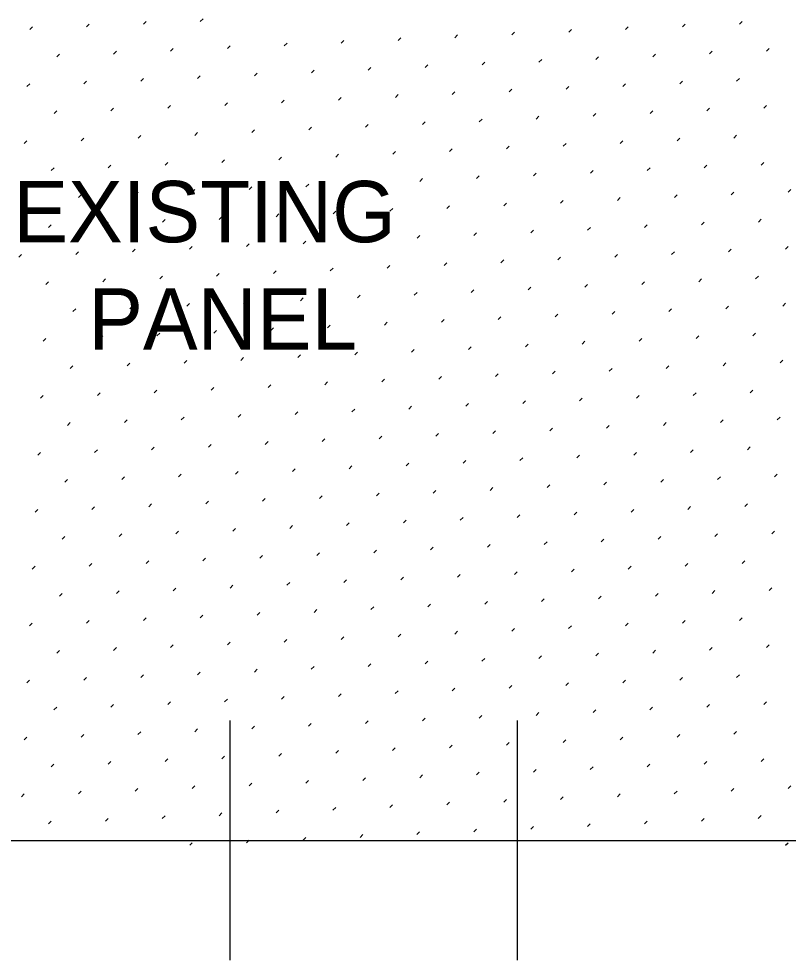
# Model space of a CAD drawing. Extents: x 49991.4 to 50021, y 49987.6 to 50011.4.
# Drawn here: x 50006.722 to 50007.726, y 49996.134 to 49997.362 of the extents above; entities that cross this region are included whole.
import ezdxf

# ---------------------------------------------------------------- set-up
doc = ezdxf.new("R2010")
doc.units = 0
for name, color, linetype in [('Level 1', 7, 'Continuous'), ('Level 10', 7, 'Continuous'), ('Level 2', 7, 'Continuous'), ('Level 4', 7, 'Continuous')]:
    doc.layers.add(name, color=color, linetype=linetype)

msp = doc.modelspace()

# ---------------------------------------------------------------- linework, layer by layer
at = {"layer": 'Level 1'}
msp.add_line((50002.3098, 49996.2901), (50007.9348, 49996.2901), dxfattribs=at)
at = {"layer": 'Level 10'}
for p, q in [((50006.7362, 49997.3477), (50006.7397, 49997.3512)), ((50006.8104, 49997.3512), (50006.814, 49997.3548)), ((50006.8847, 49997.3548), (50006.8882, 49997.3583)), ((50006.9589, 49997.3583), (50006.9625, 49997.3619)), ((50007.5141, 49997.3478), (50007.5176, 49997.3513)), ((50007.5883, 49997.3513), (50007.5919, 49997.3548)), ((50007.6626, 49997.3548), (50007.6661, 49997.3584)), ((50007.2913, 49997.3371), (50007.2948, 49997.3407)), ((50007.3656, 49997.3407), (50007.3691, 49997.3442)), ((50007.4398, 49997.3442), (50007.4433, 49997.3478)), ((50006.9943, 49997.323), (50006.9978, 49997.3265)), ((50007.0685, 49997.3265), (50007.0721, 49997.33)), ((50007.1428, 49997.3301), (50007.1463, 49997.3336)), ((50007.2171, 49997.3336), (50007.2206, 49997.3371)), ((50006.7715, 49997.3123), (50006.7751, 49997.3159)), ((50006.8458, 49997.3159), (50006.8493, 49997.3194)), ((50006.92, 49997.3194), (50006.9236, 49997.323)), ((50007.5494, 49997.3124), (50007.553, 49997.3159)), ((50007.6237, 49997.316), (50007.6272, 49997.3195)), ((50007.6979, 49997.3195), (50007.7015, 49997.323)), ((50007.2524, 49997.2982), (50007.2559, 49997.3018)), ((50007.3267, 49997.3018), (50007.3302, 49997.3053)), ((50007.4009, 49997.3053), (50007.4045, 49997.3089)), ((50007.4752, 49997.3089), (50007.4787, 49997.3124)), ((50007.0296, 49997.2876), (50007.0332, 49997.2911)), ((50007.1039, 49997.2912), (50007.1074, 49997.2947)), ((50007.1782, 49997.2947), (50007.1817, 49997.2982)), ((50006.7326, 49997.2734), (50006.7362, 49997.277)), ((50006.8069, 49997.277), (50006.8104, 49997.2805)), ((50006.8811, 49997.2805), (50006.8847, 49997.2841)), ((50006.9554, 49997.2841), (50006.9589, 49997.2876)), ((50007.5105, 49997.2735), (50007.5141, 49997.277)), ((50007.5848, 49997.2771), (50007.5883, 49997.2806)), ((50007.659, 49997.2806), (50007.6626, 49997.2841)), ((50007.2878, 49997.2629), (50007.2913, 49997.2664)), ((50007.362, 49997.2664), (50007.3656, 49997.27)), ((50007.4363, 49997.27), (50007.4398, 49997.2735)), ((50006.9908, 49997.2487), (50006.9943, 49997.2522)), ((50007.065, 49997.2523), (50007.0685, 49997.2558)), ((50007.1393, 49997.2558), (50007.1428, 49997.2593)), ((50007.2135, 49997.2593), (50007.217, 49997.2629)), ((50006.768, 49997.2381), (50006.7715, 49997.2416)), ((50006.8422, 49997.2416), (50006.8458, 49997.2452)), ((50006.9165, 49997.2452), (50006.92, 49997.2487)), ((50007.5459, 49997.2382), (50007.5494, 49997.2417)), ((50007.6201, 49997.2417), (50007.6237, 49997.2452)), ((50007.6944, 49997.2452), (50007.6979, 49997.2488)), ((50007.3231, 49997.2275), (50007.3267, 49997.2311)), ((50007.3974, 49997.2311), (50007.4009, 49997.2346)), ((50007.4716, 49997.2346), (50007.4752, 49997.2381)), ((50007.0261, 49997.2134), (50007.0296, 49997.2169)), ((50007.1004, 49997.2169), (50007.1039, 49997.2204)), ((50007.1746, 49997.2204), (50007.1781, 49997.224)), ((50007.2489, 49997.224), (50007.2524, 49997.2275)), ((50006.8033, 49997.2027), (50006.8069, 49997.2063)), ((50006.8776, 49997.2063), (50006.8811, 49997.2098)), ((50006.9519, 49997.2098), (50006.9554, 49997.2133)), ((50007.5812, 49997.2028), (50007.5848, 49997.2063)), ((50007.6555, 49997.2063), (50007.659, 49997.2099)), ((50006.7291, 49997.1992), (50006.7326, 49997.2027)), ((50007.2842, 49997.1886), (50007.2878, 49997.1922)), ((50007.3585, 49997.1922), (50007.362, 49997.1957)), ((50007.4327, 49997.1957), (50007.4363, 49997.1992)), ((50007.507, 49997.1993), (50007.5105, 49997.2028)), ((50007.0615, 49997.178), (50007.065, 49997.1815)), ((50007.1357, 49997.1815), (50007.1393, 49997.1851)), ((50007.21, 49997.1851), (50007.2135, 49997.1886)), ((50006.7644, 49997.1638), (50006.768, 49997.1674)), ((50006.8387, 49997.1674), (50006.8422, 49997.1709)), ((50006.913, 49997.1709), (50006.9165, 49997.1745)), ((50006.9872, 49997.1745), (50006.9907, 49997.178)), ((50007.5423, 49997.1639), (50007.5459, 49997.1674)), ((50007.6166, 49997.1674), (50007.6201, 49997.171)), ((50007.6908, 49997.171), (50007.6944, 49997.1745)), ((50007.3196, 49997.1533), (50007.3231, 49997.1568)), ((50007.3938, 49997.1568), (50007.3974, 49997.1604)), ((50007.4681, 49997.1604), (50007.4716, 49997.1639)), ((50007.0226, 49997.1391), (50007.0261, 49997.1426)), ((50007.0968, 49997.1426), (50007.1004, 49997.1462)), ((50007.1711, 49997.1462), (50007.1746, 49997.1497)), ((50007.2453, 49997.1497), (50007.2489, 49997.1533)), ((50006.7998, 49997.1285), (50006.8033, 49997.132)), ((50006.8741, 49997.132), (50006.8776, 49997.1356)), ((50006.9483, 49997.1356), (50006.9518, 49997.1391)), ((50007.5777, 49997.1285), (50007.5812, 49997.1321)), ((50007.6519, 49997.1321), (50007.6555, 49997.1356)), ((50007.7262, 49997.1356), (50007.7297, 49997.1392)), ((50006.7256, 49997.1249), (50006.7291, 49997.1285)), ((50007.2807, 49997.1144), (50007.2842, 49997.1179)), ((50007.3549, 49997.1179), (50007.3585, 49997.1215)), ((50007.4292, 49997.1215), (50007.4327, 49997.125)), ((50007.5034, 49997.125), (50007.507, 49997.1285)), ((50007.0579, 49997.1037), (50007.0615, 49997.1073)), ((50007.1322, 49997.1073), (50007.1357, 49997.1108)), ((50007.2064, 49997.1108), (50007.21, 49997.1144)), ((50006.7609, 49997.0896), (50006.7644, 49997.0931)), ((50006.8352, 49997.0931), (50006.8387, 49997.0967)), ((50006.9094, 49997.0967), (50006.9129, 49997.1002)), ((50006.9837, 49997.1002), (50006.9872, 49997.1037)), ((50007.5388, 49997.0896), (50007.5423, 49997.0932)), ((50007.613, 49997.0932), (50007.6166, 49997.0967)), ((50007.6873, 49997.0967), (50007.6908, 49997.1003)), ((50007.316, 49997.079), (50007.3196, 49997.0826)), ((50007.3903, 49997.0826), (50007.3938, 49997.0861)), ((50007.4645, 49997.0861), (50007.4681, 49997.0896)), ((50007.019, 49997.0648), (50007.0226, 49997.0684)), ((50007.0933, 49997.0684), (50007.0968, 49997.0719)), ((50007.1675, 49997.0719), (50007.1711, 49997.0755)), ((50007.2418, 49997.0755), (50007.2453, 49997.079)), ((50006.7963, 49997.0542), (50006.7998, 49997.0578)), ((50006.8705, 49997.0578), (50006.874, 49997.0613)), ((50006.9448, 49997.0613), (50006.9483, 49997.0648)), ((50007.5741, 49997.0543), (50007.5777, 49997.0578)), ((50007.6484, 49997.0578), (50007.6519, 49997.0614)), ((50007.7227, 49997.0614), (50007.7262, 49997.0649)), ((50006.722, 49997.0507), (50006.7255, 49997.0542)), ((50007.2771, 49997.0401), (50007.2807, 49997.0437)), ((50007.3514, 49997.0437), (50007.3549, 49997.0472)), ((50007.4256, 49997.0472), (50007.4292, 49997.0507)), ((50007.4999, 49997.0508), (50007.5034, 49997.0543)), ((50007.0544, 49997.0295), (50007.0579, 49997.033)), ((50007.1286, 49997.033), (50007.1322, 49997.0366)), ((50007.2029, 49997.0366), (50007.2064, 49997.0401)), ((50006.8316, 49997.0189), (50006.8352, 49997.0224)), ((50006.9059, 49997.0224), (50006.9094, 49997.0259)), ((50006.9801, 49997.026), (50006.9837, 49997.0295)), ((50007.5353, 49997.0154), (50007.5388, 49997.0189)), ((50007.6095, 49997.0189), (50007.613, 49997.0225)), ((50007.6838, 49997.0225), (50007.6873, 49997.026)), ((50006.7574, 49997.0153), (50006.7609, 49997.0189)), ((50007.3125, 49997.0048), (50007.316, 49997.0083)), ((50007.3867, 49997.0083), (50007.3903, 49997.0118)), ((50007.461, 49997.0119), (50007.4645, 49997.0154)), ((50007.0897, 49996.9941), (50007.0933, 49996.9977)), ((50007.164, 49996.9977), (50007.1675, 49997.0012)), ((50007.2382, 49997.0012), (50007.2418, 49997.0048)), ((50006.7927, 49996.98), (50006.7963, 49996.9835)), ((50006.867, 49996.9835), (50006.8705, 49996.987)), ((50006.9412, 49996.9871), (50006.9448, 49996.9906)), ((50007.0155, 49996.9906), (50007.019, 49996.9941)), ((50007.5706, 49996.98), (50007.5741, 49996.9836)), ((50007.6449, 49996.9836), (50007.6484, 49996.9871)), ((50007.7191, 49996.9871), (50007.7226, 49996.9907)), ((50007.3478, 49996.9694), (50007.3514, 49996.9729)), ((50007.4221, 49996.973), (50007.4256, 49996.9765)), ((50007.4964, 49996.9765), (50007.4999, 49996.98)), ((50007.0508, 49996.9552), (50007.0544, 49996.9588)), ((50007.1251, 49996.9588), (50007.1286, 49996.9623)), ((50007.1993, 49996.9623), (50007.2029, 49996.9659)), ((50007.2736, 49996.9659), (50007.2771, 49996.9694)), ((50006.8281, 49996.9446), (50006.8316, 49996.9481)), ((50006.9023, 49996.9482), (50006.9059, 49996.9517)), ((50006.9766, 49996.9517), (50006.9801, 49996.9552)), ((50007.606, 49996.9447), (50007.6095, 49996.9482)), ((50007.6802, 49996.9482), (50007.6838, 49996.9518)), ((50006.7538, 49996.9411), (50006.7574, 49996.9446)), ((50007.3089, 49996.9305), (50007.3125, 49996.934)), ((50007.3832, 49996.9341), (50007.3867, 49996.9376)), ((50007.4575, 49996.9376), (50007.461, 49996.9411)), ((50007.5317, 49996.9411), (50007.5352, 49996.9447)), ((50007.0862, 49996.9199), (50007.0897, 49996.9234)), ((50007.1604, 49996.9234), (50007.164, 49996.927)), ((50007.2347, 49996.927), (50007.2382, 49996.9305)), ((50006.7892, 49996.9057), (50006.7927, 49996.9093)), ((50006.8634, 49996.9093), (50006.867, 49996.9128)), ((50006.9377, 49996.9128), (50006.9412, 49996.9163)), ((50007.0119, 49996.9163), (50007.0155, 49996.9199)), ((50007.5671, 49996.9058), (50007.5706, 49996.9093)), ((50007.6413, 49996.9093), (50007.6449, 49996.9129)), ((50007.7156, 49996.9129), (50007.7191, 49996.9164)), ((50007.3443, 49996.8952), (50007.3478, 49996.8987)), ((50007.4186, 49996.8987), (50007.4221, 49996.9022)), ((50007.4928, 49996.9022), (50007.4963, 49996.9058)), ((50007.0473, 49996.881), (50007.0508, 49996.8845)), ((50007.1215, 49996.8845), (50007.1251, 49996.8881)), ((50007.1958, 49996.8881), (50007.1993, 49996.8916)), ((50007.2701, 49996.8916), (50007.2736, 49996.8952)), ((50006.8245, 49996.8704), (50006.8281, 49996.8739)), ((50006.8988, 49996.8739), (50006.9023, 49996.8774)), ((50006.973, 49996.8774), (50006.9766, 49996.881)), ((50007.6024, 49996.8704), (50007.606, 49996.874)), ((50007.6767, 49996.874), (50007.6802, 49996.8775)), ((50006.7503, 49996.8668), (50006.7538, 49996.8704)), ((50007.3054, 49996.8563), (50007.3089, 49996.8598)), ((50007.3797, 49996.8598), (50007.3832, 49996.8633)), ((50007.4539, 49996.8633), (50007.4574, 49996.8669)), ((50007.5282, 49996.8669), (50007.5317, 49996.8704)), ((50007.0826, 49996.8456), (50007.0862, 49996.8492)), ((50007.1569, 49996.8492), (50007.1604, 49996.8527)), ((50007.2312, 49996.8527), (50007.2347, 49996.8563)), ((50006.7856, 49996.8315), (50006.7892, 49996.835)), ((50006.8599, 49996.835), (50006.8634, 49996.8385)), ((50006.9341, 49996.8385), (50006.9377, 49996.8421)), ((50007.0084, 49996.8421), (50007.0119, 49996.8456)), ((50007.5635, 49996.8315), (50007.5671, 49996.8351)), ((50007.6378, 49996.8351), (50007.6413, 49996.8386)), ((50007.712, 49996.8386), (50007.7156, 49996.8422)), ((50007.3408, 49996.8209), (50007.3443, 49996.8244)), ((50007.415, 49996.8244), (50007.4186, 49996.828)), ((50007.4893, 49996.828), (50007.4928, 49996.8315)), ((50007.0437, 49996.8067), (50007.0473, 49996.8103)), ((50007.118, 49996.8103), (50007.1215, 49996.8138)), ((50007.1923, 49996.8138), (50007.1958, 49996.8174)), ((50007.2665, 49996.8174), (50007.27, 49996.8209)), ((50006.821, 49996.7961), (50006.8245, 49996.7996)), ((50006.8952, 49996.7996), (50006.8988, 49996.8032)), ((50006.9695, 49996.8032), (50006.973, 49996.8067)), ((50007.5989, 49996.7962), (50007.6024, 49996.7997)), ((50007.6731, 49996.7997), (50007.6767, 49996.8033)), ((50006.7467, 49996.7926), (50006.7503, 49996.7961)), ((50007.3761, 49996.7855), (50007.3797, 49996.7891)), ((50007.4504, 49996.7891), (50007.4539, 49996.7926)), ((50007.5246, 49996.7926), (50007.5282, 49996.7962)), ((50007.0791, 49996.7714), (50007.0826, 49996.7749)), ((50007.1534, 49996.7749), (50007.1569, 49996.7785)), ((50007.2276, 49996.7785), (50007.2311, 49996.782)), ((50007.3019, 49996.782), (50007.3054, 49996.7855)), ((50006.8563, 49996.7608), (50006.8599, 49996.7643)), ((50006.9306, 49996.7643), (50006.9341, 49996.7678)), ((50007.0049, 49996.7678), (50007.0084, 49996.7714)), ((50007.6342, 49996.7608), (50007.6378, 49996.7644)), ((50007.7085, 49996.7644), (50007.712, 49996.7679)), ((50006.7821, 49996.7572), (50006.7856, 49996.7607)), ((50007.3372, 49996.7467), (50007.3408, 49996.7502)), ((50007.4115, 49996.7502), (50007.415, 49996.7537)), ((50007.4857, 49996.7537), (50007.4893, 49996.7573)), ((50007.56, 49996.7573), (50007.5635, 49996.7608)), ((50007.1145, 49996.736), (50007.118, 49996.7396)), ((50007.1887, 49996.7396), (50007.1922, 49996.7431)), ((50007.263, 49996.7431), (50007.2665, 49996.7466)), ((50006.8174, 49996.7219), (50006.821, 49996.7254)), ((50006.8917, 49996.7254), (50006.8952, 49996.7289)), ((50006.966, 49996.7289), (50006.9695, 49996.7325)), ((50007.0402, 49996.7325), (50007.0437, 49996.736)), ((50007.5953, 49996.7219), (50007.5989, 49996.7255)), ((50007.6696, 49996.7255), (50007.6731, 49996.729)), ((50006.7432, 49996.7183), (50006.7467, 49996.7218)), ((50007.3726, 49996.7113), (50007.3761, 49996.7148)), ((50007.4468, 49996.7148), (50007.4504, 49996.7184)), ((50007.5211, 49996.7184), (50007.5246, 49996.7219)), ((50007.0756, 49996.6971), (50007.0791, 49996.7007)), ((50007.1498, 49996.7007), (50007.1533, 49996.7042)), ((50007.2241, 49996.7042), (50007.2276, 49996.7077)), ((50007.2983, 49996.7078), (50007.3019, 49996.7113)), ((50006.8528, 49996.6865), (50006.8563, 49996.69)), ((50006.9271, 49996.69), (50006.9306, 49996.6936)), ((50007.0013, 49996.6936), (50007.0048, 49996.6971)), ((50007.6307, 49996.6866), (50007.6342, 49996.6901)), ((50007.7049, 49996.6901), (50007.7085, 49996.6936)), ((50006.7785, 49996.683), (50006.7821, 49996.6865)), ((50007.3337, 49996.6724), (50007.3372, 49996.6759)), ((50007.4079, 49996.6759), (50007.4115, 49996.6795)), ((50007.4822, 49996.6795), (50007.4857, 49996.683)), ((50007.5564, 49996.683), (50007.56, 49996.6866)), ((50007.1109, 49996.6618), (50007.1145, 49996.6653)), ((50007.1852, 49996.6653), (50007.1887, 49996.6688)), ((50007.2594, 49996.6689), (50007.263, 49996.6724)), ((50006.8139, 49996.6476), (50006.8174, 49996.6511)), ((50006.8882, 49996.6511), (50006.8917, 49996.6547)), ((50006.9624, 49996.6547), (50006.9659, 49996.6582)), ((50007.0367, 49996.6582), (50007.0402, 49996.6618)), ((50007.5918, 49996.6477), (50007.5953, 49996.6512)), ((50007.666, 49996.6512), (50007.6696, 49996.6547)), ((50006.7396, 49996.6441), (50006.7432, 49996.6476)), ((50007.369, 49996.637), (50007.3726, 49996.6406)), ((50007.4433, 49996.6406), (50007.4468, 49996.6441)), ((50007.5175, 49996.6441), (50007.5211, 49996.6477)), ((50007.072, 49996.6229), (50007.0756, 49996.6264)), ((50007.1463, 49996.6264), (50007.1498, 49996.63)), ((50007.2205, 49996.63), (50007.2241, 49996.6335)), ((50007.2948, 49996.6335), (50007.2983, 49996.637)), ((50006.8493, 49996.6122), (50006.8528, 49996.6158)), ((50006.9235, 49996.6158), (50006.927, 49996.6193)), ((50006.9978, 49996.6193), (50007.0013, 49996.6229)), ((50007.6271, 49996.6123), (50007.6307, 49996.6159)), ((50007.7014, 49996.6159), (50007.7049, 49996.6194)), ((50006.775, 49996.6087), (50006.7785, 49996.6122)), ((50007.3301, 49996.5981), (50007.3337, 49996.6017)), ((50007.4044, 49996.6017), (50007.4079, 49996.6052)), ((50007.4786, 49996.6052), (50007.4822, 49996.6088)), ((50007.5529, 49996.6088), (50007.5564, 49996.6123)), ((50007.1074, 49996.5875), (50007.1109, 49996.5911)), ((50007.1816, 49996.5911), (50007.1852, 49996.5946)), ((50007.2559, 49996.5946), (50007.2594, 49996.5981)), ((50006.8104, 49996.5733), (50006.8139, 49996.5769)), ((50006.8846, 49996.5769), (50006.8881, 49996.5804)), ((50006.9589, 49996.5804), (50006.9624, 49996.584)), ((50007.0331, 49996.584), (50007.0367, 49996.5875)), ((50007.5882, 49996.5734), (50007.5918, 49996.577)), ((50007.6625, 49996.577), (50007.666, 49996.5805)), ((50006.7361, 49996.5698), (50006.7396, 49996.5733)), ((50007.3655, 49996.5628), (50007.369, 49996.5663)), ((50007.4397, 49996.5663), (50007.4433, 49996.5699)), ((50007.514, 49996.5699), (50007.5175, 49996.5734)), ((50007.1427, 49996.5522), (50007.1463, 49996.5557)), ((50007.217, 49996.5557), (50007.2205, 49996.5592)), ((50007.2912, 49996.5592), (50007.2948, 49996.5628)), ((50006.8457, 49996.538), (50006.8493, 49996.5415)), ((50006.92, 49996.5415), (50006.9235, 49996.5451)), ((50006.9942, 49996.5451), (50006.9978, 49996.5486)), ((50007.0685, 49996.5486), (50007.072, 49996.5522)), ((50007.6236, 49996.5381), (50007.6271, 49996.5416)), ((50007.6979, 49996.5416), (50007.7014, 49996.5451)), ((50006.7715, 49996.5344), (50006.775, 49996.538)), ((50007.4008, 49996.5274), (50007.4044, 49996.531)), ((50007.4751, 49996.531), (50007.4786, 49996.5345)), ((50007.5494, 49996.5345), (50007.5529, 49996.5381)), ((50007.1038, 49996.5133), (50007.1074, 49996.5168)), ((50007.1781, 49996.5168), (50007.1816, 49996.5203)), ((50007.2523, 49996.5203), (50007.2559, 49996.5239)), ((50007.3266, 49996.5239), (50007.3301, 49996.5274)), ((50006.8811, 49996.5026), (50006.8846, 49996.5062)), ((50006.9553, 49996.5062), (50006.9589, 49996.5097)), ((50007.0296, 49996.5097), (50007.0331, 49996.5133)), ((50007.659, 49996.5027), (50007.6625, 49996.5062)), ((50006.7326, 49996.4956), (50006.7361, 49996.4991)), ((50006.8068, 49996.4991), (50006.8104, 49996.5026)), ((50007.3619, 49996.4885), (50007.3655, 49996.4921)), ((50007.4362, 49996.4921), (50007.4397, 49996.4956)), ((50007.5105, 49996.4956), (50007.514, 49996.4992)), ((50007.5847, 49996.4992), (50007.5882, 49996.5027)), ((50007.1392, 49996.4779), (50007.1427, 49996.4814)), ((50007.2134, 49996.4815), (50007.217, 49996.485)), ((50007.2877, 49996.485), (50007.2912, 49996.4885)), ((50006.8422, 49996.4637), (50006.8457, 49996.4673)), ((50006.9164, 49996.4673), (50006.92, 49996.4708)), ((50006.9907, 49996.4708), (50006.9942, 49996.4744)), ((50007.0649, 49996.4744), (50007.0685, 49996.4779)), ((50007.6201, 49996.4638), (50007.6236, 49996.4673)), ((50007.6943, 49996.4674), (50007.6979, 49996.4709)), ((50006.7679, 49996.4602), (50006.7715, 49996.4637)), ((50007.3973, 49996.4532), (50007.4008, 49996.4567)), ((50007.4716, 49996.4567), (50007.4751, 49996.4603)), ((50007.5458, 49996.4603), (50007.5493, 49996.4638)), ((50007.1003, 49996.439), (50007.1038, 49996.4425)), ((50007.1745, 49996.4426), (50007.1781, 49996.4461)), ((50007.2488, 49996.4461), (50007.2523, 49996.4496)), ((50007.323, 49996.4496), (50007.3266, 49996.4532)), ((50006.8775, 49996.4284), (50006.8811, 49996.4319)), ((50006.9518, 49996.4319), (50006.9553, 49996.4355)), ((50007.026, 49996.4355), (50007.0296, 49996.439)), ((50007.6554, 49996.4285), (50007.659, 49996.432)), ((50006.729, 49996.4213), (50006.7326, 49996.4248)), ((50006.8033, 49996.4248), (50006.8068, 49996.4284)), ((50007.3584, 49996.4143), (50007.3619, 49996.4178)), ((50007.4327, 49996.4178), (50007.4362, 49996.4214)), ((50007.5069, 49996.4214), (50007.5104, 49996.4249)), ((50007.5812, 49996.4249), (50007.5847, 49996.4284)), ((50007.1356, 49996.4037), (50007.1392, 49996.4072)), ((50007.2099, 49996.4072), (50007.2134, 49996.4107)), ((50007.2842, 49996.4107), (50007.2877, 49996.4143)), ((50006.8386, 49996.3895), (50006.8422, 49996.393)), ((50006.9129, 49996.393), (50006.9164, 49996.3966)), ((50006.9871, 49996.3966), (50006.9907, 49996.4001)), ((50007.0614, 49996.4001), (50007.0649, 49996.4036)), ((50007.6165, 49996.3896), (50007.6201, 49996.3931)), ((50007.6908, 49996.3931), (50007.6943, 49996.3966)), ((50006.7644, 49996.3859), (50006.7679, 49996.3895)), ((50007.3938, 49996.3789), (50007.3973, 49996.3825)), ((50007.468, 49996.3825), (50007.4715, 49996.386)), ((50007.5423, 49996.386), (50007.5458, 49996.3895)), ((50007.0967, 49996.3648), (50007.1003, 49996.3683)), ((50007.171, 49996.3683), (50007.1745, 49996.3718)), ((50007.2453, 49996.3718), (50007.2488, 49996.3754)), ((50007.3195, 49996.3754), (50007.323, 49996.3789)), ((50006.874, 49996.3541), (50006.8775, 49996.3577)), ((50006.9482, 49996.3577), (50006.9518, 49996.3612)), ((50007.0225, 49996.3612), (50007.026, 49996.3648)), ((50007.6519, 49996.3542), (50007.6554, 49996.3577)), ((50007.7261, 49996.3577), (50007.7297, 49996.3613)), ((50006.7255, 49996.347), (50006.729, 49996.3506)), ((50006.7997, 49996.3506), (50006.8033, 49996.3541)), ((50007.3549, 49996.34), (50007.3584, 49996.3436)), ((50007.4291, 49996.3436), (50007.4326, 49996.3471)), ((50007.5034, 49996.3471), (50007.5069, 49996.3507)), ((50007.5776, 49996.3507), (50007.5812, 49996.3542)), ((50007.1321, 49996.3294), (50007.1356, 49996.3329)), ((50007.2064, 49996.3329), (50007.2099, 49996.3365)), ((50007.2806, 49996.3365), (50007.2841, 49996.34)), ((50006.9093, 49996.3188), (50006.9129, 49996.3223)), ((50006.9836, 49996.3223), (50006.9871, 49996.3259)), ((50007.0578, 49996.3259), (50007.0614, 49996.3294)), ((50007.6872, 49996.3188), (50007.6908, 49996.3224)), ((50006.7608, 49996.3117), (50006.7644, 49996.3152)), ((50006.8351, 49996.3152), (50006.8386, 49996.3188)), ((50007.3902, 49996.3047), (50007.3938, 49996.3082)), ((50007.4645, 49996.3082), (50007.468, 49996.3118)), ((50007.5387, 49996.3118), (50007.5423, 49996.3153)), ((50007.613, 49996.3153), (50007.6165, 49996.3188)), ((50007.1675, 49996.294), (50007.171, 49996.2976)), ((50007.2417, 49996.2976), (50007.2452, 49996.3011)), ((50007.316, 49996.3011), (50007.3195, 49996.3047)), ((50006.9451, 49996.2838), (50006.9482, 49996.287)), ((50007.019, 49996.287), (50007.0225, 49996.2905)), ((50007.0932, 49996.2905), (50007.0967, 49996.294)), ((50007.7229, 49996.2838), (50007.7261, 49996.287))]:
    msp.add_line(p, q, dxfattribs=at)
at = {"layer": 'Level 4'}
for p, q in [((50006.9973, 49996.4463), (50006.9973, 49996.1338)), ((50007.3723, 49996.4463), (50007.3723, 49996.1338))]:
    msp.add_line(p, q, dxfattribs=at)

# ---------------------------------------------------------------- texts
at = {"layer": 'Level 2'}
for s, p in [('EXISTING', (50006.7149, 49997.0703)), ('PANEL', (50006.8127, 49996.9303))]:
    msp.add_text(s, height=0.08, dxfattribs=at).set_placement(p)

doc.saveas('drawing.dxf')
